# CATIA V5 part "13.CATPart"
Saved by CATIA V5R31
Part number: 1x13
Definition: 13M Beam 4522937/41239
Nomenclature: 13M Beam 4522937/41239
Source: Unknown
Bounding box of the stored display mesh (mm): x -0.1 to 7.103, y -3.6 to 99.6, z 0 to 8
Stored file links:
  C:\Users\super\Desktop\LEGO\TFG-2621\TFG_02621_anejos\13.CATPart
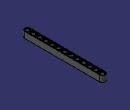
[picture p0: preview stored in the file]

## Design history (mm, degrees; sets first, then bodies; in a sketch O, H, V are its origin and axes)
AxisSystem1: origin (0, 0, 0), X (1, 0, 0), Y (0, 1, 0), Z (0, 0, 1)
Body1 "Body1" (main body)
  Solid1: solid without history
